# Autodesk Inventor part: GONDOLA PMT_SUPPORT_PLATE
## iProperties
Shininess: 64.0
Length Units: 11272
Angle Units: 11279
Time Units: 11290
Mass Units: 11286
Length Display Precision: 3
Angle Display Precision: 2
Compacted: True
Part Number: GONDOLA PMT_SUPPORT_PLATE
Document SubType Name: Modeling
Created: 2004-08
Designer: John Blackburn
Manufacturer: Standard
Standards Organization: Custom
Density: 0.0
Volumn: 0.0
Area: 0.0
PropertySet Name: Model Information
Control State: 0
Master: False
Checked Out: False
Author: John Blackburn
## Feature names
1. ExtrusionBlind1
2. AM_HOLE_SI0030_1 [Hole]
3. AM_HOLE_SI0030_2 [Hole]
4. AM_HOLE_SI0030_3 [Hole]
5. AM_HOLE_SI0030_4 [Hole]
